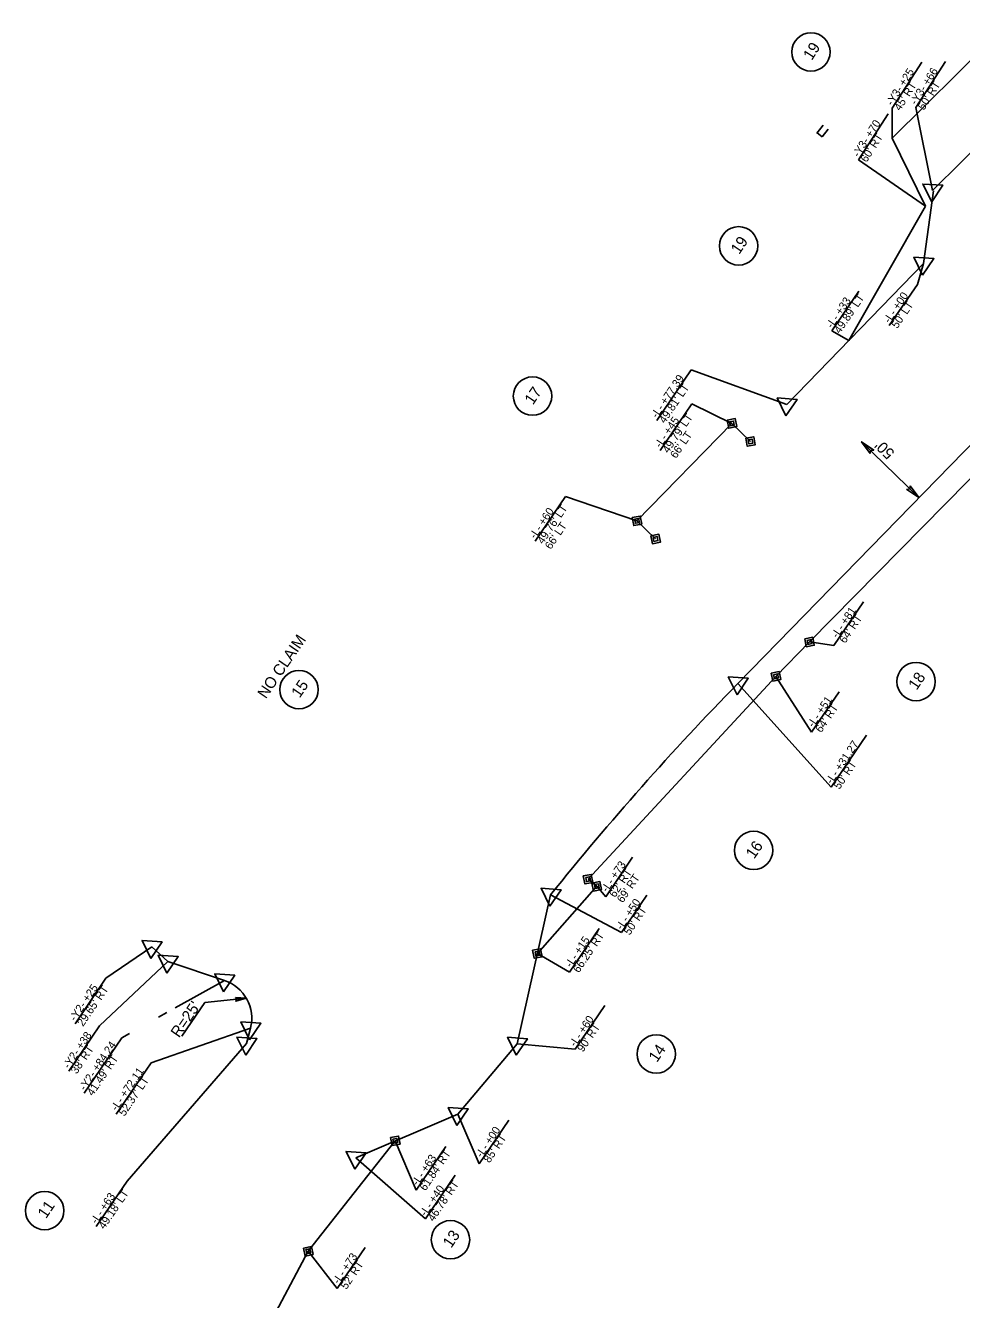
# Model space of a CAD drawing. Extents: x 1975689 to 1978251, y 778490 to 782347.
# Drawn here: x 1976157 to 1976742, y 779284 to 780080 of the extents above; entities that cross this region are included whole.
import ezdxf

# ---------------------------------------------------------------- set-up
doc = ezdxf.new("R2010")
doc.units = 0
for name, color, linetype in [('Default', 7, 'Continuous'), ('Old_Level_8', 7, 'Continuous'), ('Prop Dimension', 7, 'Continuous'), ('Prop Dimension Text', 7, 'Continuous'), ('Prop Easement Aerial Utility', 7, 'Continuous'), ('Prop Easement Aerial Utility Station Offsets', 7, 'Continuous'), ('Prop Easement Construction', 7, 'Continuous'), ('Prop Easement Construction Station Offsets', 7, 'Continuous'), ('Prop Easement Permanent Utility', 7, 'Continuous'), ('Prop Easement Permanent Utility Station Offsets', 7, 'Continuous'), ('Prop Parcel Number CELL', 7, 'Continuous'), ('Prop ROW Marker CELL', 7, 'Continuous'), ('Prop ROW Permanent Easement CELL', 7, 'Continuous'), ('Prop ROW RW Lines', 7, 'Continuous'), ('Prop ROW Station Offsets', 7, 'Continuous'), ('Prop ROW Text', 7, 'Continuous'), ('Prop Terminator CELL', 7, 'Continuous'), ('Scratch_Level_1', 7, 'Continuous')]:
    doc.layers.add(name, color=color, linetype=linetype)

msp = doc.modelspace()

# ---------------------------------------------------------------- linework, layer by layer
at = {"layer": 'Default'}
for p, q in [((1976651.65, 780013.04), (1976655.33, 780017.82)), ((1976654.77, 780010.64), (1976658.45, 780015.42))]:
    msp.add_line(p, q, dxfattribs=at)
at = {"layer": 'Old_Level_8'}
for points in [[(1976651.2, 780013.39), (1976651.65, 780013.04)], [(1976651.65, 780013.04), (1976654.77, 780010.64)]]:
    msp.add_lwpolyline(points, dxfattribs=at)
at = {"layer": 'Prop Dimension'}
for p, q in [((1976254.64, 779448.7), (1976269.05, 779469.72)), ((1976269.05, 779469.72), (1976294.98, 779472.37))]:
    msp.add_line(p, q, dxfattribs=at)
at = {"layer": 'Prop Easement Aerial Utility'}
for p, q in [((1976539, 779770.64), (1976598.32, 779831.51)), ((1976598.32, 779831.51), (1976609.93, 779820.2)), ((1976550.63, 779759.3), (1976539, 779770.64))]:
    msp.add_line(p, q, dxfattribs=at)
at = {"layer": 'Prop Easement Aerial Utility Station Offsets'}
for p, q in [((1976553.55, 779814.68), (1976573.32, 779843.73)), ((1976598.32, 779831.51), (1976573.32, 779843.73)), ((1976475.3, 779757.86), (1976494.31, 779785.78)), ((1976494.31, 779785.78), (1976539, 779770.64))]:
    msp.add_line(p, q, dxfattribs=at)
at = {"layer": 'Prop Easement Construction'}
for p, q in [((1976698.3, 780009.8), (1976769.35, 780080.17)), ((1976719.31, 779967.27), (1976698.3, 780009.8)), ((1976671.27, 779883.29), (1976719.31, 779967.27))]:
    msp.add_line(p, q, dxfattribs=at)
at = {"layer": 'Prop Easement Construction Station Offsets'}
for p, q in [((1976698.3, 780028.46), (1976716.86, 780057.22)), ((1976677.34, 779996.27), (1976695.9, 780025.02)), ((1976698.3, 780028.46), (1976698.3, 780009.8)), ((1976677.34, 779996.27), (1976719.31, 779967.27)), ((1976660.76, 779889.38), (1976677.67, 779914.23)), ((1976660.76, 779889.38), (1976671.27, 779883.29))]:
    msp.add_line(p, q, dxfattribs=at)
at = {"layer": 'Prop Easement Permanent Utility'}
for p, q in [((1976646.76, 779694.95), (1976800.32, 779851.09)), ((1976625.82, 779673.46), (1976646.76, 779694.95)), ((1976508.45, 779546.76), (1976625.82, 779673.46)), ((1976513.85, 779542.3), (1976508.45, 779546.76)), ((1976476.8, 779500.31), (1976513.85, 779542.3)), ((1976333.69, 779314.24), (1976388.05, 779383.25)), ((1976268.28, 779192.01), (1976333.69, 779314.24))]:
    msp.add_line(p, q, dxfattribs=at)
at = {"layer": 'Prop Easement Permanent Utility Station Offsets'}
for p, q in [((1976662.06, 779692.83), (1976680.47, 779719.96)), ((1976646.76, 779694.95), (1976662.06, 779692.83)), ((1976625.82, 779673.46), (1976648.02, 779638.51)), ((1976648.02, 779638.51), (1976665.24, 779663.89)), ((1976519.48, 779535.79), (1976536.2, 779560.42)), ((1976513.85, 779542.3), (1976519.48, 779535.79)), ((1976496.9, 779488.72), (1976515.4, 779516)), ((1976476.8, 779500.31), (1976496.9, 779488.72)), ((1976388.05, 779383.25), (1976401.09, 779352.47)), ((1976401.09, 779352.47), (1976419.6, 779379.74)), ((1976351.76, 779290.92), (1976369.21, 779316.64)), ((1976333.69, 779314.24), (1976351.76, 779290.92))]:
    msp.add_line(p, q, dxfattribs=at)
at = {"layer": 'Prop Parcel Number CELL'}
for p, q in [((1976647.66, 780063.64), (1976647.66, 780063.64)), ((1976602.48, 779942.46), (1976602.48, 779942.46)), ((1976473.75, 779848.58), (1976473.75, 779848.58)), ((1976327.88, 779665.17), (1976327.88, 779665.17)), ((1976713.35, 779670.22), (1976713.35, 779670.22)), ((1976611.86, 779564.74), (1976611.86, 779564.74)), ((1976551.02, 779437.49), (1976551.02, 779437.49)), ((1976169.03, 779339.63), (1976169.03, 779339.63)), ((1976422.52, 779321.44), (1976422.52, 779321.44))]:
    msp.add_line(p, q, dxfattribs=at)
for centre in [(1976647.66, 780063.64), (1976602.48, 779942.46), (1976473.75, 779848.58), (1976713.35, 779670.22), (1976327.88, 779665.17), (1976611.86, 779564.74), (1976551.02, 779437.49), (1976169.03, 779339.63), (1976422.52, 779321.44)]:
    msp.add_circle(centre, 12, dxfattribs=at)
at = {"layer": 'Prop ROW Marker CELL'}
for p, q in [((1976723.6, 779977.15), (1976723.6, 779977.15)), ((1976717.96, 779931.35), (1976717.96, 779931.35)), ((1976632.53, 779843.41), (1976632.53, 779843.41)), ((1976598.32, 779831.51), (1976598.32, 779831.51)), ((1976609.93, 779820.2), (1976609.93, 779820.2)), ((1976539, 779770.64), (1976539, 779770.64)), ((1976550.63, 779759.3), (1976550.63, 779759.3)), ((1976646.76, 779694.95), (1976646.76, 779694.95)), ((1976625.82, 779673.46), (1976625.82, 779673.46)), ((1976602.02, 779669.1), (1976602.02, 779669.1)), ((1976508.45, 779546.76), (1976508.45, 779546.76)), ((1976513.85, 779542.3), (1976513.85, 779542.3)), ((1976485.05, 779537.02), (1976485.05, 779537.02)), ((1976235.85, 779504.41), (1976235.85, 779504.41)), ((1976476.8, 779500.31), (1976476.8, 779500.31)), ((1976245.96, 779495.23), (1976245.96, 779495.23)), ((1976281.25, 779483.51), (1976281.25, 779483.51)), ((1976297.58, 779453.54), (1976297.58, 779453.54)), ((1976295.11, 779443.97), (1976295.11, 779443.97)), ((1976464.12, 779443.89), (1976464.12, 779443.89)), ((1976427.06, 779399.98), (1976427.06, 779399.98)), ((1976388.05, 779383.25), (1976388.05, 779383.25)), ((1976363.29, 779372.63), (1976363.29, 779372.63)), ((1976333.69, 779314.24), (1976333.69, 779314.24))]:
    msp.add_line(p, q, dxfattribs=at)
for points in [[(1976723.24, 779969.95), (1976717.55, 779981.06), (1976730.02, 779980.45)], [(1976717.42, 779924.16), (1976712.01, 779935.4), (1976724.45, 779934.49)], [(1976631.99, 779836.21), (1976626.57, 779847.46), (1976639.02, 779846.55)], [(1976601.49, 779661.91), (1976596.06, 779673.14), (1976608.51, 779672.25)], [(1976484.52, 779529.82), (1976479.1, 779541.06), (1976491.54, 779540.17)], [(1976235.31, 779497.22), (1976229.9, 779508.46), (1976242.34, 779507.55)], [(1976245.42, 779488.04), (1976240.01, 779499.28), (1976252.45, 779498.37)], [(1976280.71, 779476.32), (1976275.3, 779487.57), (1976287.74, 779486.66)], [(1976297.04, 779446.35), (1976291.63, 779457.59), (1976304.07, 779456.68)], [(1976294.57, 779436.77), (1976289.15, 779448.02), (1976301.6, 779447.11)], [(1976463.59, 779436.69), (1976458.16, 779447.93), (1976470.6, 779447.04)], [(1976426.53, 779392.79), (1976421.1, 779404.03), (1976433.55, 779403.13)], [(1976362.76, 779365.44), (1976357.33, 779376.67), (1976369.78, 779375.78)]]:
    msp.add_lwpolyline(points, close=True, dxfattribs=at)
at = {"layer": 'Prop ROW Permanent Easement CELL'}
for points in [[(1976595.34, 779833.53), (1976600.34, 779834.49), (1976601.3, 779829.49), (1976596.3, 779828.53)], [(1976596.83, 779832.52), (1976599.33, 779833), (1976599.81, 779830.5), (1976597.31, 779830.02)], [(1976606.95, 779822.22), (1976611.95, 779823.18), (1976612.91, 779818.18), (1976607.91, 779817.22)], [(1976608.44, 779821.21), (1976610.94, 779821.69), (1976611.42, 779819.19), (1976608.92, 779818.71)], [(1976536.02, 779772.66), (1976541.02, 779773.62), (1976541.98, 779768.62), (1976536.98, 779767.66)], [(1976537.51, 779771.65), (1976540.01, 779772.13), (1976540.49, 779769.63), (1976537.99, 779769.15)], [(1976547.65, 779761.33), (1976552.65, 779762.28), (1976553.61, 779757.28), (1976548.61, 779756.32)], [(1976549.14, 779760.31), (1976551.64, 779760.79), (1976552.12, 779758.29), (1976549.62, 779757.81)], [(1976643.78, 779696.97), (1976648.78, 779697.93), (1976649.74, 779692.93), (1976644.74, 779691.97)], [(1976645.27, 779695.96), (1976647.77, 779696.44), (1976648.25, 779693.94), (1976645.75, 779693.46)], [(1976622.84, 779675.48), (1976627.84, 779676.44), (1976628.8, 779671.44), (1976623.8, 779670.48)], [(1976624.33, 779674.47), (1976626.83, 779674.95), (1976627.31, 779672.45), (1976624.81, 779671.97)], [(1976505.47, 779548.78), (1976510.47, 779549.73), (1976511.43, 779544.73), (1976506.43, 779543.78)], [(1976506.96, 779547.77), (1976509.46, 779548.24), (1976509.94, 779545.75), (1976507.44, 779545.27)], [(1976510.87, 779544.33), (1976515.88, 779545.28), (1976516.83, 779540.28), (1976511.83, 779539.33)], [(1976512.36, 779543.31), (1976514.86, 779543.79), (1976515.34, 779541.29), (1976512.84, 779540.81)], [(1976473.82, 779502.33), (1976478.82, 779503.29), (1976479.78, 779498.29), (1976474.78, 779497.33)], [(1976475.31, 779501.32), (1976477.81, 779501.8), (1976478.29, 779499.3), (1976475.79, 779498.82)], [(1976385.07, 779385.27), (1976390.07, 779386.23), (1976391.03, 779381.23), (1976386.03, 779380.27)], [(1976386.56, 779384.26), (1976389.06, 779384.74), (1976389.54, 779382.24), (1976387.04, 779381.76)], [(1976330.71, 779316.26), (1976335.71, 779317.22), (1976336.67, 779312.22), (1976331.67, 779311.26)], [(1976332.2, 779315.25), (1976334.7, 779315.73), (1976335.18, 779313.23), (1976332.68, 779312.75)]]:
    msp.add_lwpolyline(points, close=True, dxfattribs=at)
at = {"layer": 'Prop ROW RW Lines'}
for p, q in [((1976723.6, 779977.15), (1976794.65, 780047.52)), ((1976724.29, 779976.8), (1976717.96, 779931.35)), ((1976632.53, 779843.41), (1976717.96, 779931.35)), ((1976602.02, 779669.1), (1976837, 779910.23)), ((1976464.12, 779443.89), (1976485.05, 779537.02)), ((1976245.96, 779495.23), (1976235.85, 779504.41)), ((1976245.96, 779495.23), (1976281.25, 779483.51)), ((1976295.11, 779443.97), (1976297.58, 779453.54)), ((1976427.06, 779399.98), (1976464.12, 779443.89)), ((1976363.29, 779372.63), (1976427.06, 779399.98))]:
    msp.add_line(p, q, dxfattribs=at)
for centre, radius, start, end in [((1977926.94, 778377.94), 1850, 135.73946, 141.20569), ((1976273.37, 779459.79), 25, 345.52479, 71.63322)]:
    msp.add_arc(centre, radius, start, end, dxfattribs=at)
at = {"layer": 'Prop ROW Station Offsets'}
for p, q in [((1976713.17, 780028.9), (1976731.73, 780057.65)), ((1976723.6, 779977.15), (1976713.17, 780028.9)), ((1976714.13, 779918.37), (1976717.96, 779931.35)), ((1976696.6, 779892.61), (1976714.13, 779918.37)), ((1976551.36, 779833.27), (1976572.95, 779865.01)), ((1976572.95, 779865.01), (1976632.53, 779843.41)), ((1976660.27, 779604.16), (1976602.02, 779669.1)), ((1976660.27, 779604.16), (1976682.34, 779636.69)), ((1976529.42, 779513.39), (1976485.05, 779537.02)), ((1976529.42, 779513.39), (1976545.24, 779536.71)), ((1976207.28, 779484.79), (1976235.85, 779504.41)), ((1976203.3, 779455.1), (1976245.96, 779495.23)), ((1976187.99, 779456.45), (1976207.28, 779484.79)), ((1976250.63, 779466.35), (1976281.25, 779483.51)), ((1976500.34, 779440.45), (1976518.84, 779467.73)), ((1976240.13, 779460.46), (1976245.38, 779463.4)), ((1976184.01, 779426.75), (1976203.3, 779455.1)), ((1976217.22, 779447.61), (1976222.07, 779450.33)), ((1976235.52, 779432.03), (1976297.58, 779453.54)), ((1976193.72, 779413.09), (1976217.22, 779447.61)), ((1976220.55, 779358.12), (1976295.11, 779443.97)), ((1976500.34, 779440.45), (1976464.12, 779443.89)), ((1976213.64, 779399.89), (1976235.52, 779432.03)), ((1976440.4, 779368.83), (1976427.06, 779399.98)), ((1976440.4, 779368.83), (1976458.91, 779396.1)), ((1976406.99, 779334.54), (1976363.29, 779372.63)), ((1976201.26, 779329.78), (1976220.55, 779358.12)), ((1976406.99, 779334.54), (1976425.5, 779361.82))]:
    msp.add_line(p, q, dxfattribs=at)
at = {"layer": 'Prop ROW Text'}
msp.add_line((1976715.09, 779785.13), (1976679.28, 779820.02), dxfattribs=at)
at = {"layer": 'Prop Terminator CELL'}
for points in [[(1976684.65, 779812.63), (1976679.28, 779820.02), (1976686.88, 779814.85), (1976684.94, 779814.51)], [(1976709.73, 779792.52), (1976715.09, 779785.13), (1976707.49, 779790.3), (1976709.43, 779790.64)], [(1976288.14, 779472.84), (1976294.98, 779472.37), (1976288.34, 779470.49), (1976289.08, 779471.77)]]:
    msp.add_lwpolyline(points, close=True, dxfattribs=at)
at = {"layer": 'Scratch_Level_1'}
msp.add_line((1976363.29, 779372.63), (1976363.29, 779372.63), dxfattribs=at)
msp.add_line((1976363.29, 779372.63), (1976363.29, 779372.63), dxfattribs=at)

# ---------------------------------------------------------------- texts
at = {"layer": 'Prop Dimension Text'}
msp.add_text("R=25'", height=7, rotation=55.58051, dxfattribs=at).set_placement((1976252.92, 779447.22))
at = {"layer": 'Prop Easement Aerial Utility Station Offsets'}
for s, p in [('-L- +45', (1976553.68, 779815.85)), ("49.79' LT", (1976558.56, 779812.53)), ("66' LT", (1976563.43, 779809.22)), ('-L- +60', (1976475.44, 779759.03)), ("49.76' LT", (1976480.31, 779755.71)), ("66' LT", (1976485.18, 779752.4))]:
    msp.add_text(s, height=5, rotation=55.75919, dxfattribs=at).set_placement(p)
at = {"layer": 'Prop Easement Construction Station Offsets'}
for s, rotation, p in [('-Y3- +25', 57.15853, (1976698.4, 780029.63)), ("45' RT", 57.15853, (1976703.36, 780026.44)), ('-Y3- +70', 57.15853, (1976677.44, 779997.44)), ("60' RT", 57.15853, (1976682.39, 779994.24)), ("49.89' LT", 55.75919, (1976665.76, 779887.23)), ('-L- +33', 55.75919, (1976660.89, 779890.55))]:
    msp.add_text(s, height=5, rotation=rotation, dxfattribs=at).set_placement(p)
at = {"layer": 'Prop Easement Permanent Utility Station Offsets'}
for s, p in [('-L- +81', (1976664.16, 779696.99)), ("64' RT", (1976669.03, 779693.69)), ('-L- +51', (1976649.18, 779641.21)), ("64' RT", (1976654.06, 779637.9)), ('-L- +73', (1976520.38, 779538.19)), ("62' RT", (1976525.25, 779534.88)), ("69' RT", (1976530.13, 779531.57)), ("66.25' RT", (1976502.67, 779487.82)), ('-L- +15', (1976497.79, 779491.13)), ('-L- +63', (1976401.99, 779354.87)), ("61.84' RT", (1976406.87, 779351.56)), ('-L- +73', (1976352.65, 779293.32)), ("52' RT", (1976357.53, 779290.01))]:
    msp.add_text(s, height=5, rotation=55.84408, dxfattribs=at).set_placement(p)
at = {"layer": 'Prop Parcel Number CELL'}
for s, rotation, p in [('19', 57.28837, (1976648.17, 780057.94)), ('19', 55.84408, (1976602.84, 779936.73)), ('17', 55.84408, (1976473.99, 779842.67)), ('NO CLAIM', 55.84408, (1976307.2, 779659.05)), ('18', 55.84408, (1976713.69, 779664.45)), ('15', 55.84408, (1976328.29, 779659.52)), ('16', 55.84408, (1976612.21, 779558.99)), ('14', 55.84408, (1976551.47, 779431.88)), ('11', 55.84408, (1976169.85, 779334.24)), ('13', 55.84408, (1976422.94, 779315.8))]:
    msp.add_text(s, height=7, rotation=rotation, dxfattribs=at).set_placement(p)
at = {"layer": 'Prop ROW Station Offsets'}
for s, rotation, p in [('-Y3- +66', 57.15853, (1976713.28, 780030.07)), ("50' RT", 57.15853, (1976718.23, 780026.87)), ('-L- +00', 55.75919, (1976696.73, 779893.77)), ("50' LT", 55.75919, (1976701.6, 779890.46)), ('-L- +77.39', 55.75919, (1976551.49, 779834.44)), ("49.81' LT", 55.75919, (1976556.36, 779831.12)), ('-L- +31.27', 55.84408, (1976660.62, 779605.77)), ("50' RT", 55.84408, (1976665.5, 779602.46)), ('-L- +50', 55.84408, (1976529.56, 779514.68)), ("50' RT", 55.84408, (1976534.43, 779511.37)), ('-Y2- +25', 55.75919, (1976188.12, 779457.62)), ("29.65' RT", 55.75919, (1976192.99, 779454.3)), ('-L- +60', 55.84408, (1976500.4, 779441.63)), ('-Y2- +38', 55.75919, (1976184.14, 779427.92)), ("90' RT", 55.84408, (1976505.28, 779438.32)), ("38' RT", 55.75919, (1976189.01, 779424.6)), ('-Y2- +84.24', 55.75919, (1976194.2, 779414.24)), ("41.49' RT", 55.75919, (1976199.08, 779410.92)), ('-L- +72.11', 55.75919, (1976214.01, 779401.57)), ("52.37' LT", 55.75919, (1976218.88, 779398.25)), ('-L- +00', 55.84408, (1976441.98, 779372.32)), ("85' RT", 55.84408, (1976446.86, 779369.01)), ('-L- +40', 55.84408, (1976407.05, 779335.72)), ("46.78' RT", 55.84408, (1976411.93, 779332.41)), ('-L- +63', 55.75919, (1976201.4, 779330.95)), ("49.18' LT", 55.75919, (1976206.27, 779327.63))]:
    msp.add_text(s, height=5, rotation=rotation, dxfattribs=at).set_placement(p)
at = {"layer": 'Prop ROW Text'}
msp.add_text("50'", height=7, rotation=135.73946, dxfattribs=at).set_placement((1976700.42, 779813.43))

doc.saveas('drawing.dxf')
